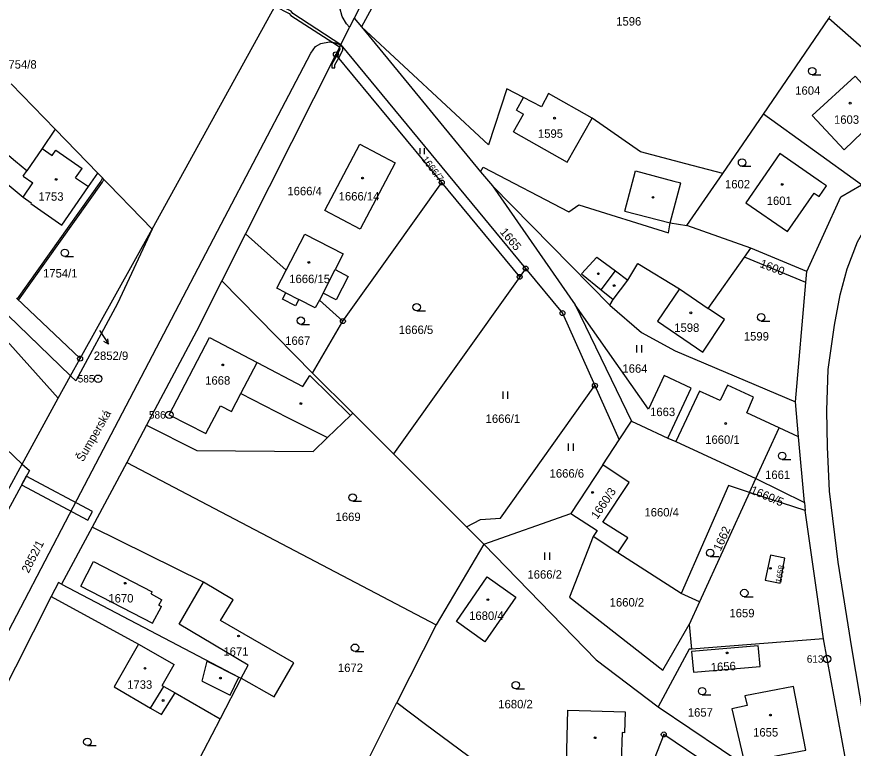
# Model space of a CAD drawing. Extents: x -562167 to -556918, y -1077891 to -1070763.
# Drawn here: x -560237.8 to -560069.1, y -1075869.3 to -1075721.8 of the extents above; entities that cross this region are included whole.
import ezdxf

# ---------------------------------------------------------------- set-up
doc = ezdxf.new("R2010")
doc.units = 0
for name, color, linetype in [('Hranice parcel', 7, 'Continuous'), ('Parcelní čísla', 7, 'Continuous'), ('Pop  PČ popisy', 7, 'Continuous'), ('Vnitřní kresba', 7, 'Continuous'), ('Věcná břemena k části', 7, 'Continuous'), ('Značky bodu BP', 7, 'Continuous'), ('Značky budov', 7, 'Continuous'), ('Značky kultur', 7, 'Continuous')]:
    doc.layers.add(name, color=color, linetype=linetype)

msp = doc.modelspace()

# ---------------------------------------------------------------- linework, layer by layer
at = {"layer": 'Hranice parcel'}
for p, q in [((-560159.58, -1075707.9), (-560168.31, -1075723.85)), ((-560210.52, -1075764.64), (-560183.67, -1075715.89)), ((-560074.03, -1075722.18), (-560073.78, -1075721.61)), ((-560169.77, -1075722.07), (-560170.71, -1075723.93)), ((-560169.77, -1075722.07), (-560168.31, -1075723.85)), ((-560087.25, -1075741.43), (-560074.03, -1075722.18)), ((-560052.57, -1075741.18), (-560074.03, -1075722.18)), ((-560172.47, -1075727.43), (-560170.71, -1075723.93)), ((-560168.31, -1075723.85), (-560144.32, -1075753.08)), ((-560172.47, -1075727.43), (-560173.45, -1075729.38)), ((-560172.47, -1075727.43), (-560135.19, -1075772.55)), ((-560152.11, -1075755.21), (-560173.45, -1075729.38)), ((-560230.06, -1075744.47), (-560238.91, -1075735.33)), ((-560095.46, -1075753.39), (-560087.25, -1075741.43)), ((-560067.45, -1075755.71), (-560087.25, -1075741.43)), ((-560221.47, -1075753.33), (-560230.06, -1075744.47)), ((-560210.52, -1075764.64), (-560221.47, -1075753.33)), ((-560144.32, -1075753.08), (-560141.89, -1075755.91)), ((-560102.68, -1075763.91), (-560095.46, -1075753.39)), ((-560136.39, -1075774.23), (-560152.11, -1075755.21)), ((-560141.89, -1075755.91), (-560118.19, -1075779.93)), ((-560141.89, -1075755.91), (-560125.2, -1075779.9)), ((-560089.78, -1075768.42), (-560102.68, -1075763.91)), ((-560225.01, -1075790.71), (-560210.52, -1075764.64)), ((-560191.67, -1075765.53), (-560196.46, -1075775.04)), ((-560183.48, -1075772.88), (-560191.67, -1075765.53)), ((-560255.26, -1075766.9), (-560226.93, -1075794.16)), ((-560091.08, -1075770.26), (-560089.78, -1075768.42)), ((-560078.48, -1075773.16), (-560089.78, -1075768.42)), ((-560078.68, -1075775.4), (-560091.08, -1075770.26)), ((-560135.19, -1075772.55), (-560136.39, -1075774.23)), ((-560078.68, -1075775.4), (-560078.48, -1075773.16)), ((-560196.46, -1075775.04), (-560178.17, -1075793.62)), ((-560136.39, -1075774.23), (-560161.85, -1075809.92)), ((-560080.81, -1075799.44), (-560078.68, -1075775.4)), ((-560237.87, -1075778.54), (-560225.01, -1075790.71)), ((-560172.04, -1075783.15), (-560176.78, -1075778.9)), ((-560125.2, -1075779.9), (-560113.87, -1075803.31)), ((-560178.17, -1075793.62), (-560172.04, -1075783.15)), ((-560226.93, -1075794.16), (-560225.01, -1075790.71)), ((-560257.91, -1075791.69), (-560236.7, -1075811.98)), ((-560229.42, -1075798.71), (-560226.93, -1075794.16)), ((-560170.04, -1075801.74), (-560178.17, -1075793.62)), ((-560121.22, -1075796.16), (-560116.33, -1075807.07)), ((-560236.7, -1075811.98), (-560229.42, -1075798.71)), ((-560080.17, -1075806.5), (-560080.81, -1075799.44)), ((-560161.85, -1075809.92), (-560170.04, -1075801.74)), ((-560211.65, -1075804.15), (-560215.63, -1075811.65)), ((-560116.33, -1075807.07), (-560113.87, -1075803.31)), ((-560088.8, -1075814.86), (-560084.08, -1075804.66)), ((-560080.17, -1075806.5), (-560084.08, -1075804.66)), ((-560119.6, -1075812.1), (-560116.33, -1075807.07)), ((-560106.5, -1075806.72), (-560104.9, -1075807.45)), ((-560104.9, -1075807.45), (-560088.8, -1075814.86)), ((-560078.98, -1075819.69), (-560080.17, -1075806.5)), ((-560161.85, -1075809.92), (-560147.14, -1075824.61)), ((-560248.49, -1075833.57), (-560236.7, -1075811.98)), ((-560215.63, -1075811.65), (-560222.59, -1075824.66)), ((-560215.63, -1075811.65), (-560153.26, -1075844.35)), ((-560119.6, -1075812.1), (-560126.06, -1075821.93)), ((-560090.08, -1075817.67), (-560088.8, -1075814.86)), ((-560088.8, -1075814.86), (-560078.98, -1075819.69)), ((-560090.08, -1075817.67), (-560100.17, -1075839.72)), ((-560078.84, -1075821.3), (-560090.08, -1075817.67)), ((-560078.98, -1075819.69), (-560078.84, -1075821.3)), ((-560075.13, -1075847.2), (-560078.84, -1075821.3)), ((-560143.65, -1075828.09), (-560126.06, -1075821.93)), ((-560222.59, -1075824.66), (-560228.74, -1075836.15)), ((-560200.16, -1075835.8), (-560222.59, -1075824.66)), ((-560143.65, -1075828.09), (-560147.14, -1075824.61)), ((-560143.65, -1075828.09), (-560153.26, -1075844.35)), ((-560143.65, -1075828.09), (-560120.96, -1075851.41)), ((-560116.61, -1075829.83), (-560121.6, -1075826.6)), ((-560103.83, -1075838.03), (-560116.61, -1075829.83)), ((-560100.17, -1075839.72), (-560103.83, -1075838.03)), ((-560230.82, -1075838.69), (-560248.25, -1075872.91)), ((-560100.17, -1075839.72), (-560102.25, -1075844.33)), ((-560153.26, -1075844.35), (-560161.16, -1075860.03)), ((-560102.25, -1075844.33), (-560101.77, -1075849.27)), ((-560075.13, -1075847.2), (-560101.77, -1075849.27)), ((-560120.96, -1075851.41), (-560108.49, -1075860.9)), ((-560192.54, -1075855.15), (-560196.78, -1075863.31)), ((-560171.4, -1075880.35), (-560161.16, -1075860.03)), ((-560161.16, -1075860.03), (-560155.41, -1075864.37)), ((-560155.41, -1075864.37), (-560117.51, -1075892.34))]:
    msp.add_line(p, q, dxfattribs=at)
for points in [[(-560170.71, -1075723.93), (-560171.34, -1075723.24), (-560172.18, -1075721.74), (-560172.67, -1075720.03), (-560172.57, -1075718.58), (-560172.02, -1075716.72), (-560164.42, -1075702.22), (-560143.59, -1075662.47), (-560140.58, -1075656.65), (-560139.8, -1075655.62), (-560138.56, -1075654.71), (-560136.89, -1075653.98), (-560134.96, -1075653.67), (-560132.8, -1075653.95), (-560130.94, -1075654.25)], [(-560159.58, -1075707.9), (-560161.95, -1075706.6), (-560169.77, -1075722.07)], [(-560095.46, -1075753.39), (-560102.91, -1075751.42), (-560112.02, -1075749.02), (-560121.76, -1075742.22), (-560130.57, -1075737.24), (-560131.98, -1075739.94), (-560135.61, -1075738.05), (-560138.97, -1075736.35), (-560142.7, -1075747.64), (-560168.31, -1075723.85)], [(-560282.12, -1075934.51), (-560283, -1075932.25), (-560283.08, -1075930.01), (-560282.46, -1075927.75), (-560280.62, -1075924.18), (-560265.72, -1075895.71), (-560246.83, -1075859.69), (-560227.16, -1075822.08), (-560208.85, -1075787.15), (-560196.56, -1075763.61), (-560182.19, -1075736.22), (-560178.49, -1075729.15), (-560177.53, -1075727.83), (-560176.47, -1075727.17), (-560174.73, -1075726.87), (-560173.46, -1075727.12), (-560172.47, -1075727.43)], [(-560173.45, -1075729.38), (-560186.92, -1075756.1), (-560191.67, -1075765.53)], [(-560065.45, -1075743.35), (-560064.1, -1075744.82), (-560061.09, -1075742.09), (-560068.74, -1075733.77), (-560077.39, -1075741.71), (-560070.99, -1075748.65), (-560065.45, -1075743.35)], [(-560230.06, -1075744.47), (-560232.69, -1075748.35), (-560235.75, -1075752.86), (-560238.02, -1075750.97), (-560244.83, -1075745.28), (-560247.66, -1075748.84), (-560240.94, -1075754.46), (-560236.52, -1075758.15), (-560234.86, -1075759.32), (-560234.94, -1075759.43), (-560228.69, -1075763.82), (-560223.34, -1075756.05), (-560221.47, -1075753.33)], [(-560168.57, -1075764.65), (-560175.68, -1075760.87), (-560168.61, -1075747.46), (-560161.48, -1075751.22), (-560168.57, -1075764.65)], [(-560083.91, -1075749.36), (-560090.8, -1075759.33), (-560082.41, -1075765.12), (-560077.03, -1075757.36), (-560076.03, -1075758.05), (-560074.52, -1075755.87), (-560075.52, -1075755.18), (-560083.91, -1075749.36)], [(-560144.32, -1075753.08), (-560143.77, -1075752.12), (-560126.49, -1075761.12), (-560124.44, -1075759.69), (-560106.38, -1075765.33), (-560106.05, -1075763.36), (-560102.68, -1075763.91)], [(-560172.04, -1075783.15), (-560162.13, -1075769.26), (-560152.11, -1075755.21)], [(-560078.48, -1075773.16), (-560071.67, -1075758.12), (-560067.45, -1075755.71)], [(-560055.8, -1075912.37), (-560060.46, -1075895.76), (-560063.07, -1075884.26), (-560065.43, -1075872.49), (-560069.44, -1075848.98), (-560072.17, -1075831.75), (-560073.93, -1075817.46), (-560074.34, -1075808.46), (-560074.45, -1075801.18), (-560074.17, -1075792.89), (-560072.93, -1075783.94), (-560071.76, -1075777.87), (-560070.38, -1075772.61), (-560068.31, -1075767.18), (-560065.69, -1075762.57)], [(-560210.52, -1075764.64), (-560217.5, -1075779.63), (-560225.85, -1075795.16), (-560226.93, -1075794.16)], [(-560183.48, -1075772.88), (-560179.71, -1075765.62), (-560171.97, -1075769.62), (-560173.6, -1075772.77), (-560170.95, -1075774.14), (-560173.4, -1075778.86), (-560176.04, -1075777.49), (-560176.78, -1075778.9)], [(-560118.19, -1075779.93), (-560117.54, -1075778.81), (-560114.61, -1075774.9), (-560112.54, -1075771.57), (-560104.16, -1075776.66), (-560108.61, -1075783.19), (-560099.44, -1075789.42), (-560095.13, -1075782.8), (-560098.4, -1075780.58), (-560091.08, -1075770.26)], [(-560176.78, -1075778.9), (-560177.62, -1075780.49), (-560180.91, -1075778.79), (-560181.58, -1075780.09), (-560184.24, -1075778.73), (-560183.56, -1075777.42), (-560185.36, -1075776.51), (-560183.48, -1075772.88)], [(-560135.19, -1075772.55), (-560127.76, -1075781.54), (-560121.22, -1075796.16)], [(-560196.46, -1075775.04), (-560201.57, -1075785.18), (-560211.65, -1075804.15)], [(-560106.5, -1075806.72), (-560101.79, -1075796.65), (-560107.25, -1075794.13), (-560110.45, -1075800.92), (-560125.2, -1075779.9)], [(-560118.19, -1075779.93), (-560111.81, -1075785.43), (-560105.05, -1075789.12), (-560080.81, -1075799.44)], [(-560260.62, -1075789.1), (-560260.57, -1075789.05), (-560258.06, -1075786.39), (-560256.01, -1075786.35), (-560248.01, -1075791.8), (-560242.69, -1075783.98), (-560229.42, -1075798.71)], [(-560084.08, -1075804.66), (-560090.61, -1075801.65), (-560089.23, -1075798.5), (-560094.52, -1075796.06), (-560095.98, -1075799.16), (-560100.13, -1075797.24), (-560104.9, -1075807.45)], [(-560147.14, -1075824.61), (-560144.31, -1075823.15), (-560140.27, -1075822.86), (-560121.22, -1075796.16)], [(-560211.65, -1075804.15), (-560201.47, -1075809.21), (-560178.01, -1075809.42), (-560175.13, -1075806.64), (-560170.49, -1075802.18), (-560170.04, -1075801.74)], [(-560113.87, -1075803.31), (-560111.99, -1075804.18), (-560106.5, -1075806.72)], [(-560236.7, -1075811.98), (-560235.23, -1075813.27), (-560246.96, -1075834.84), (-560248.49, -1075833.57)], [(-560116.61, -1075829.83), (-560114.59, -1075826.84), (-560119.65, -1075823.67), (-560114.33, -1075815.68), (-560119.6, -1075812.1)], [(-560090.08, -1075817.67), (-560094.3, -1075816.31), (-560103.83, -1075838.03)], [(-560126.06, -1075821.93), (-560120.8, -1075825.39), (-560121.6, -1075826.6)], [(-560121.6, -1075826.6), (-560126.37, -1075838.81), (-560107.5, -1075853.5), (-560105.23, -1075849.54), (-560102.25, -1075844.33)], [(-560083.88, -1075835.97), (-560082.93, -1075830.95), (-560085.8, -1075830.35), (-560086.87, -1075835.4), (-560083.88, -1075835.97)], [(-560149.14, -1075843.71), (-560142.98, -1075834.72), (-560137.2, -1075838.78), (-560143.44, -1075847.82), (-560149.14, -1075843.71)], [(-560228.74, -1075836.15), (-560229.36, -1075835.82), (-560230.82, -1075838.69)], [(-560228.74, -1075836.15), (-560193, -1075854.91), (-560192.54, -1075855.15)], [(-560192.54, -1075855.15), (-560191.15, -1075852.49), (-560205.06, -1075844.27), (-560200.16, -1075835.8)], [(-560192.54, -1075855.15), (-560185.92, -1075858.88), (-560181.96, -1075852.06), (-560196.72, -1075843.5), (-560194.15, -1075839.32), (-560200.16, -1075835.8)], [(-560230.82, -1075838.69), (-560213.24, -1075848.26), (-560218.13, -1075856.9), (-560210.82, -1075861.17), (-560208.6, -1075862.47), (-560205.88, -1075858.11), (-560196.78, -1075863.31)], [(-560069.18, -1075879.62), (-560069.22, -1075879.43), (-560075.13, -1075847.2)], [(-560101.77, -1075849.27), (-560102.25, -1075849.31), (-560108.49, -1075860.9)], [(-560087.89, -1075852.8), (-560088.23, -1075849.15), (-560088.28, -1075848.62), (-560101.73, -1075849.75), (-560101.38, -1075853.94), (-560087.89, -1075852.8)], [(-560081.17, -1075856.82), (-560090.97, -1075858.65), (-560090.56, -1075860.6), (-560093.6, -1075861.3), (-560091.2, -1075871.65), (-560088.37, -1075871.05), (-560088.28, -1075871.44), (-560078.72, -1075869.61), (-560081.17, -1075856.82)], [(-560123.09, -1075877.68), (-560127.12, -1075877.55), (-560126.66, -1075861.57), (-560115.13, -1075861.9), (-560115.25, -1075866.12), (-560115.75, -1075866.1), (-560116.11, -1075877.91), (-560118.59, -1075877.83), (-560119.61, -1075878.8), (-560122.13, -1075878.7), (-560123.09, -1075877.68)], [(-560108.49, -1075860.9), (-560089.3, -1075873.8), (-560078.02, -1075877.75), (-560069.18, -1075879.62)], [(-560196.78, -1075863.31), (-560203.48, -1075876.2), (-560187.34, -1075889.94)], [(-560068.11, -1075883.95), (-560079.09, -1075881.6), (-560091.1, -1075877.41), (-560107.34, -1075866.47), (-560117.51, -1075892.34)]]:
    msp.add_lwpolyline(points, dxfattribs=at)
at = {"layer": 'Pop  PČ popisy'}
for p, q in [((-560221.09, -1075785.02), (-560220.91, -1075785.3)), ((-560220.91, -1075785.3), (-560219.28, -1075787.82)), ((-560219.28, -1075787.82), (-560220.24, -1075787.25)), ((-560219.28, -1075787.82), (-560219.4, -1075786.7))]:
    msp.add_line(p, q, dxfattribs=at)
at = {"layer": 'Vnitřní kresba'}
for p, q in [((-560137.05, -1075740.62), (-560135.61, -1075738.05)), ((-560137.65, -1075745.02), (-560135.64, -1075741.47)), ((-560137.05, -1075740.62), (-560135.64, -1075741.47)), ((-560126.79, -1075751.11), (-560121.76, -1075742.22)), ((-560137.65, -1075745.02), (-560126.79, -1075751.11)), ((-560232.69, -1075748.35), (-560230.65, -1075749.78)), ((-560230.65, -1075749.78), (-560229.89, -1075748.71)), ((-560229.89, -1075748.71), (-560224.57, -1075752.4)), ((-560236.47, -1075753.94), (-560235.75, -1075752.86)), ((-560236.47, -1075753.94), (-560234.53, -1075755.31)), ((-560225.92, -1075754.27), (-560224.57, -1075752.4)), ((-560115.18, -1075760.96), (-560113.04, -1075752.88)), ((-560113.04, -1075752.88), (-560105.31, -1075754.93)), ((-560236.52, -1075758.15), (-560234.53, -1075755.31)), ((-560225.92, -1075754.27), (-560223.34, -1075756.05)), ((-560106.05, -1075763.36), (-560103.93, -1075755.29)), ((-560105.31, -1075754.93), (-560103.93, -1075755.29)), ((-560115.18, -1075760.96), (-560106.05, -1075763.36)), ((-560123.92, -1075773.63), (-560120.86, -1075770.25)), ((-560120.86, -1075770.25), (-560117.1, -1075773.05)), ((-560176.04, -1075777.49), (-560173.6, -1075772.77)), ((-560123.92, -1075773.63), (-560119.95, -1075776.86)), ((-560119.95, -1075776.86), (-560117.1, -1075773.05)), ((-560117.1, -1075773.05), (-560114.61, -1075774.9)), ((-560183.56, -1075777.42), (-560180.91, -1075778.79)), ((-560119.95, -1075776.86), (-560117.54, -1075778.81)), ((-560104.16, -1075776.66), (-560098.4, -1075780.58)), ((-560207.03, -1075802.05), (-560198.94, -1075786.46)), ((-560198.94, -1075786.46), (-560189.33, -1075791.5)), ((-560192.58, -1075797.72), (-560189.33, -1075791.5)), ((-560189.33, -1075791.5), (-560180.09, -1075796.34)), ((-560180.09, -1075796.34), (-560178.67, -1075794.13)), ((-560178.67, -1075794.13), (-560170.49, -1075802.18)), ((-560194.49, -1075801.39), (-560192.58, -1075797.72)), ((-560192.58, -1075797.72), (-560183.19, -1075802.58)), ((-560199.68, -1075805.83), (-560196.73, -1075800.23)), ((-560196.73, -1075800.23), (-560194.49, -1075801.39)), ((-560207.03, -1075802.05), (-560199.68, -1075805.83)), ((-560183.19, -1075802.58), (-560175.13, -1075806.64)), ((-560224.88, -1075836.59), (-560222.35, -1075831.63)), ((-560222.35, -1075831.63), (-560210.49, -1075837.73)), ((-560224.88, -1075836.59), (-560210.42, -1075844.05)), ((-560210.68, -1075838.1), (-560210.49, -1075837.73)), ((-560210.68, -1075838.1), (-560208.55, -1075839.34)), ((-560209.12, -1075840.44), (-560208.55, -1075839.34)), ((-560210.42, -1075844.05), (-560208.62, -1075840.7)), ((-560209.12, -1075840.44), (-560208.62, -1075840.7)), ((-560213.24, -1075848.26), (-560206.07, -1075852.35)), ((-560200.42, -1075855.75), (-560199.41, -1075851.72)), ((-560199.41, -1075851.72), (-560193, -1075854.91)), ((-560208.5, -1075856.61), (-560206.07, -1075852.35)), ((-560194.79, -1075858.58), (-560193, -1075854.91)), ((-560210.82, -1075861.17), (-560208.13, -1075856.83)), ((-560208.5, -1075856.61), (-560208.13, -1075856.83)), ((-560208.13, -1075856.83), (-560205.88, -1075858.11)), ((-560200.42, -1075855.75), (-560194.79, -1075858.58))]:
    msp.add_line(p, q, dxfattribs=at)
at = {"layer": 'Věcná břemena k části'}
for points in [[(-560185.26, -1075718.78), (-560185.75, -1075719.67), (-560182.86, -1075721.15), (-560182.53, -1075721.57), (-560174.05, -1075727), (-560173.46, -1075727.12), (-560172.47, -1075727.43), (-560182.11, -1075721.13), (-560182.46, -1075720.67), (-560185.36, -1075719.2)], [(-560172.69, -1075727.87), (-560172.47, -1075727.43), (-560173.46, -1075727.12), (-560174.05, -1075727)], [(-560172.02, -1075727.98), (-560172.47, -1075727.43), (-560172.69, -1075727.87), (-560172.63, -1075728.39), (-560173.28, -1075729.59), (-560172.87, -1075730.09), (-560172.03, -1075728.55)], [(-560172.87, -1075730.09), (-560173.28, -1075729.59), (-560174.24, -1075731.35), (-560174.25, -1075732.09), (-560173.65, -1075732.11), (-560173.64, -1075731.51)], [(-560237.43, -1075778.96), (-560220.47, -1075755.14), (-560220.23, -1075754.61), (-560220.53, -1075754.3), (-560220.82, -1075754.94), (-560237.72, -1075778.68)], [(-560223.44, -1075823.28), (-560222.5, -1075821.52), (-560235.86, -1075814.43), (-560236.81, -1075816.18)]]:
    msp.add_lwpolyline(points, close=True, dxfattribs=at)
at = {"layer": 'Značky bodu BP'}
for centre, radius in [((-560173.45, -1075729.38), 0.5), ((-560173.45, -1075729.38), 0.0303), ((-560152.11, -1075755.21), 0.5), ((-560152.11, -1075755.21), 0.0303), ((-560135.19, -1075772.55), 0.5), ((-560136.39, -1075774.23), 0.5), ((-560135.19, -1075772.55), 0.0303), ((-560136.39, -1075774.23), 0.0303), ((-560127.76, -1075781.54), 0.5), ((-560127.76, -1075781.54), 0.0303), ((-560172.04, -1075783.15), 0.5), ((-560172.04, -1075783.15), 0.0303), ((-560225.01, -1075790.71), 0.5), ((-560225.01, -1075790.71), 0.0303), ((-560221.39, -1075794.77), 0.75), ((-560221.39, -1075794.77), 0.03), ((-560121.22, -1075796.16), 0.5), ((-560121.22, -1075796.16), 0.0303), ((-560207.03, -1075802.05), 0.75), ((-560207.03, -1075802.05), 0.03), ((-560074.4, -1075851.26), 0.75), ((-560074.4, -1075851.26), 0.03), ((-560107.34, -1075866.47), 0.5), ((-560107.34, -1075866.47), 0.0303)]:
    msp.add_circle(centre, radius, dxfattribs=at)
at = {"layer": 'Značky budov'}
for centre in [(-560069.76, -1075739.22), (-560129.36, -1075742.24), (-560229.85, -1075754.59), (-560168.06, -1075754.32), (-560083.46, -1075755.6), (-560109.52, -1075758.21), (-560178.9, -1075771.33), (-560120.53, -1075773.6), (-560117.34, -1075775.99), (-560101.89, -1075781.48), (-560196.25, -1075791.98), (-560180.5, -1075799.78), (-560094.86, -1075803.79), (-560121.7, -1075817.68), (-560085.83, -1075832.99), (-560215.92, -1075835.99), (-560142.8, -1075839.3), (-560193.07, -1075846.63), (-560094.58, -1075850.03), (-560211.94, -1075853.13), (-560196.72, -1075855.11), (-560208.28, -1075859.62), (-560085.84, -1075862.56), (-560121.18, -1075867.13)]:
    msp.add_circle(centre, 0.175, dxfattribs=at)
at = {"layer": 'Značky kultur'}
for p, q in [((-560077.4, -1075733.51), (-560075.65, -1075733.51)), ((-560156.44, -1075749.52), (-560156.44, -1075748.26)), ((-560155.6, -1075749.52), (-560155.6, -1075748.26)), ((-560091.55, -1075751.95), (-560089.8, -1075751.95)), ((-560228.1, -1075770.13), (-560226.35, -1075770.13)), ((-560157.16, -1075781.1), (-560155.41, -1075781.1)), ((-560180.51, -1075783.81), (-560178.76, -1075783.81)), ((-560087.71, -1075783.13), (-560085.96, -1075783.13)), ((-560112.79, -1075789.49), (-560112.79, -1075787.99)), ((-560111.79, -1075789.49), (-560111.79, -1075787.99)), ((-560139.75, -1075798.82), (-560139.75, -1075797.32)), ((-560138.75, -1075798.82), (-560138.75, -1075797.32)), ((-560126.55, -1075809.3), (-560126.55, -1075807.8)), ((-560125.55, -1075809.3), (-560125.55, -1075807.8)), ((-560083.46, -1075811.06), (-560081.71, -1075811.06)), ((-560170.06, -1075819.46), (-560168.31, -1075819.46)), ((-560131.31, -1075831.28), (-560131.31, -1075829.78)), ((-560130.31, -1075831.28), (-560130.31, -1075829.78)), ((-560098, -1075830.62), (-560096.25, -1075830.62)), ((-560091.1, -1075838.71), (-560089.35, -1075838.71)), ((-560169.59, -1075849.74), (-560167.84, -1075849.74)), ((-560137.19, -1075857.27), (-560135.44, -1075857.27)), ((-560099.59, -1075858.49), (-560097.84, -1075858.49)), ((-560223.55, -1075868.72), (-560221.8, -1075868.72))]:
    msp.add_line(p, q, dxfattribs=at)
for centre in [(-560077.4, -1075732.76), (-560091.55, -1075751.2), (-560228.1, -1075769.38), (-560157.16, -1075780.35), (-560180.51, -1075783.06), (-560087.71, -1075782.38), (-560083.46, -1075810.31), (-560170.06, -1075818.71), (-560098, -1075829.87), (-560091.1, -1075837.96), (-560169.59, -1075848.99), (-560137.19, -1075856.52), (-560099.59, -1075857.74), (-560223.55, -1075867.97)]:
    msp.add_circle(centre, 0.75, dxfattribs=at)

# ---------------------------------------------------------------- texts
at = {"layer": 'Parcelní čísla'}
for s, p in [('1596', (-560116.93, -1075723.58)), ('1754/8', (-560240.73, -1075732.26)), ('1604', (-560080.84, -1075737.52)), ('1603', (-560073.02, -1075743.38)), ('1595', (-560132.71, -1075746.2)), ('1602', (-560095, -1075756.4)), ('1753', (-560233.42, -1075758.89)), ('1666/4', (-560183.23, -1075757.79)), ('1666/14', (-560172.89, -1075758.84)), ('1601', (-560086.59, -1075759.74)), ('1754/1', (-560232.49, -1075774.36)), ('1666/15', (-560182.85, -1075775.49)), ('1666/5', (-560160.78, -1075785.75)), ('1598', (-560105.23, -1075785.32)), ('1599', (-560091.2, -1075787.07)), ('1667', (-560183.67, -1075787.94)), ('2852/9', (-560222.27, -1075790.99)), ('1664', (-560115.68, -1075793.56)), ('1668', (-560199.8, -1075795.96)), ('1663', (-560110.1, -1075802.3)), ('1666/1', (-560143.26, -1075803.67)), ('1660/1', (-560098.99, -1075807.89)), ('1666/6', (-560130.36, -1075814.7)), ('1661', (-560086.91, -1075814.97)), ('1660/4', (-560111.24, -1075822.53)), ('1669', (-560173.51, -1075823.45)), ('1666/2', (-560134.83, -1075835.07)), ('1670', (-560219.32, -1075839.87)), ('1660/2', (-560118.25, -1075840.68)), ('1680/4', (-560146.58, -1075843.38)), ('1659', (-560094.1, -1075842.86)), ('1671', (-560196.12, -1075850.6)), ('1672', (-560173.04, -1075853.88)), ('1733', (-560215.53, -1075857.26)), ('1680/2', (-560140.71, -1075861.2)), ('1657', (-560102.49, -1075862.88)), ('1655', (-560089.33, -1075866.89))]:
    msp.add_text(s, height=1.7, dxfattribs=at).set_placement(p)
for s, height, rotation, p in [('1666/7', 1.42, 307, (-560156.23, -1075750.56)), ('1665', 1.7, 310, (-560140.47, -1075765.24)), ('1600', 1.7, 339, (-560088.12, -1075772.22)), ('1660/3', 1.7, 56, (-560120.75, -1075823.22)), ('1660/5', 1.7, 337, (-560090.02, -1075817.83)), ('1662', 1.7, 66, (-560095.88, -1075829.63)), ('2852/1', 1.7, 63, (-560235.4, -1075834.08)), ('1658', 1.2, 79, (-560083.66, -1075835.97)), ('1656', 1.7, 3, (-560097.82, -1075853.77))]:
    msp.add_text(s, height=height, rotation=rotation, dxfattribs=at).set_placement(p)
at = {"layer": 'Pop  PČ popisy'}
msp.add_text('Šumperská', height=1.7, rotation=60, dxfattribs=at).set_placement((-560224.43, -1075811.64))
at = {"layer": 'Značky bodu BP'}
for s, p in [('585', (-560225.49, -1075795.52)), ('586', (-560211.13, -1075802.8)), ('613', (-560078.5, -1075852.01))]:
    msp.add_text(s, height=1.5, dxfattribs=at).set_placement(p)

doc.saveas('drawing.dxf')
